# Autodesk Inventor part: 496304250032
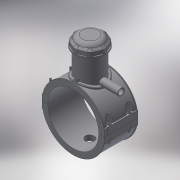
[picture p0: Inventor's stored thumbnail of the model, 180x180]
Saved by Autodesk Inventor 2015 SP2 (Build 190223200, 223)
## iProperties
Created: 2017-07
Part Number: 496304250032
Material: Generic
Description: PLASSON TAPPING SADDLE 250x32
Document SubType Name: Modeling
Designer: KIM
Mass: 1954.72 g
Surface Area: 3813.95 cm^2
Volume: 1954.72 cm^3
Density: 1 g/cm^3
Appearance: Default
Author: KIM
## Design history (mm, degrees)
derived "496304.ipt"
feature "Solid1::496304.ipt"
feature "Solid2::496304.ipt"
feature "Solid4::496304.ipt"
feature "Solid5::496304.ipt"
tag "TaggingFeature1" dims "B_" = 252
body "Solid1"
body "Solid2"
other parameters: "L_" = 176, "d_t" = 6, "H_2" = 177, "H_1" = 56, "d_1" = 32, "H_" = 132, "d1" = 285, "d148" = 3.75, "d160" = 3.75, "d169" = 3.75, "d192" = 7, "d2" = 327.6, "d3" = 62.5, "d4" = 176, "d5" = 0, "d6" = 0.1, "d8" = 0, "d19" = 6, "d20" = 6, "d21" = 105.6, "d23" = 0, "d24" = 52.8, "d26" = 0, "d29" = 3, "d30" = 83.33333, "d31" = 6, "d32" = 0, "d33" = 0, "d34" = 0.6, "d40" = 148.2, "d43" = 0, "d45" = 0, "d47" = 248.1, "d70" = 15, "d72" = 0, "d73" = 6, "d75" = 5, "d76" = 0, "d77" = 12.5, "d78" = 155, "d79" = 15, "d80" = 70.4, "d82" = 5 deg, "d84" = 4, "d85" = 14, "d86" = 0, "d87" = 3, "d88" = 0, "d89" = 1, "d90" = 1, "d91" = 140.8, "d92" = 0, "d93" = 0.5, "d94" = 131.57895, "d96" = 290.7, "d97" = 3.52, "d98" = 0, "d102" = 2.5, "d120" = 140 deg, "d121" = 24.228, "d122" = 20 deg, "d124" = 171, "d126" = 0, "d143" = 257.5, "d145" = 26.92308, "d149" = 3.75, "d150" = 29.61538, "d153" = 176, "d154" = 0, "d156" = 142.5, "d157" = 160 deg, "d159" = 7, "d161" = 3.75, "d162" = 105.6, "d163" = 0, "d164" = 125, "d167" = 25, "d168" = 139.02439, "d170" = 3.75, "d172" = 0, "d173" = 1, "d175" = 125, "d176" = 20 deg, "d177" = 17.5, "d178" = 35, "d180" = 0, "d183" = 14, "d184" = 14, "d185" = 57.2, "d186" = 57.2, "d187" = 142.5, "d188" = 10.5, "d189" = 17.5, "d190" = 0, "d191" = 213.75, "d193" = 7, "d194" = 6.16, "d195" = 90 deg, "d197" = 0, "d199" = 0, "d200" = 17.5, "d202" = 0, "d203" = 177, "d204" = 95, "d206" = 85, "d207" = 132.75, "d208" = 138.06, "d209" = 164.61, "d210" = 86, "d213" = 36, "d216" = 0, "d217" = 25, "d218" = 25, "d219" = 5, "d224" = 0, "d230" = 5, "d233" = 6, "d236" = 126, "d237" = 52.8, "d238" = 6.02433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
